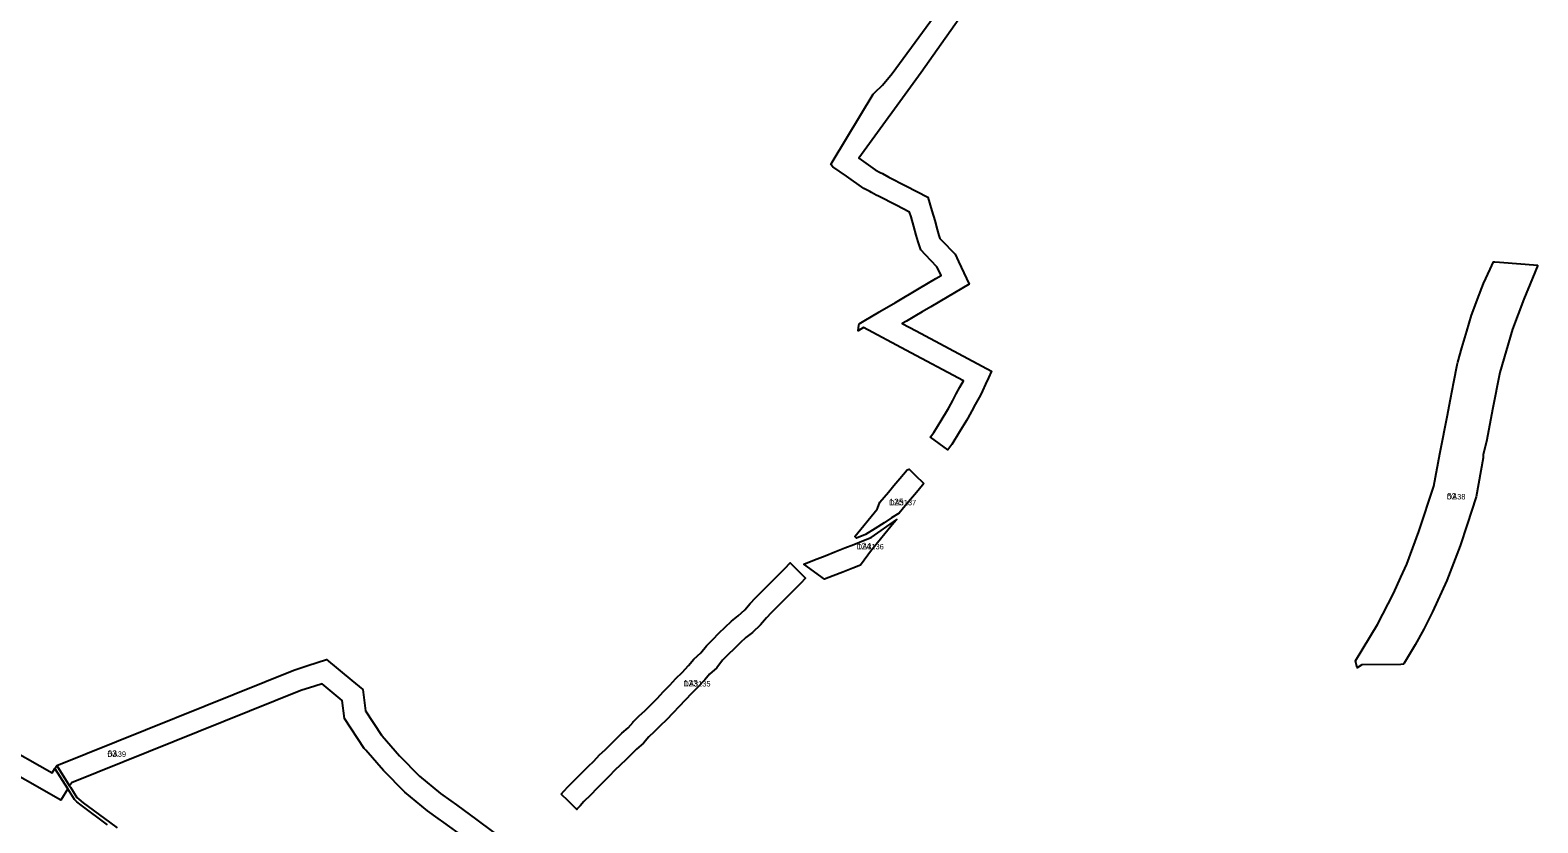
# Model space of a CAD drawing. Extents: x -537012 to -534603, y -1176562 to -1172739.
# Drawn here: x -535993 to -534603, y -1175871 to -1175140 of the extents above; entities that cross this region are included whole.
import ezdxf

# ---------------------------------------------------------------- set-up
doc = ezdxf.new("R2010")
doc.units = 0
for name, color, linetype in [('96120023', 7, 'Continuous'), ('96140023', 7, 'Continuous'), ('ID_VPO', 7, 'Continuous')]:
    doc.layers.add(name, color=color, linetype=linetype)

msp = doc.modelspace()

# ---------------------------------------------------------------- linework, layer by layer
at = {"layer": '96120023'}
msp.add_lwpolyline([(-535921.6, -1175873.09), (-535945.82, -1175855.15), (-535949.79, -1175851.94), (-535952.05, -1175849.98), (-535958.16, -1175840.1), (-535958.19, -1175840.06), (-535970.14, -1175821.39), (-535968.39, -1175818.56), (-535956.44, -1175837.23), (-535955.62, -1175838.5), (-535949.74, -1175848.02), (-535947.86, -1175849.64), (-535943.98, -1175852.77), (-535919.82, -1175870.67), (-535912.56, -1175875.93)], dxfattribs=at)
at = {"layer": '96140023'}
for points in [[(-535125.65, -1175114.54), (-535171.35, -1175179.43), (-535228.84, -1175258.49), (-535213.77, -1175269.12), (-535208.97, -1175271.6), (-535207.07, -1175272.72), (-535201.25, -1175275.98), (-535185.43, -1175284.03), (-535165.16, -1175294.32), (-535161.42, -1175307.02), (-535158.83, -1175315.85), (-535156.55, -1175324.14), (-535155.03, -1175329.66), (-535154.08, -1175332.44), (-535152.92, -1175333.64), (-535140.01, -1175347.02), (-535136.92, -1175353.62), (-535127.13, -1175374.47), (-535147.45, -1175386.52), (-535162.53, -1175395.44), (-535170.42, -1175400.1), (-535177.19, -1175404.11), (-535184.79, -1175408.61), (-535188.76, -1175410.94), (-535176.04, -1175417.7), (-535106.48, -1175454.72), (-535106.52, -1175454.81), (-535109.28, -1175460.96), (-535111.87, -1175466.75), (-535114.68, -1175473.01), (-535115.02, -1175473.77), (-535117.96, -1175479.18), (-535121.39, -1175485.47), (-535124.69, -1175491.52), (-535128.36, -1175498.25), (-535129.49, -1175500.32), (-535135.96, -1175510.86), (-535143.17, -1175522.62), (-535146.84, -1175527.49), (-535162.85, -1175515.62), (-535162.81, -1175515.45), (-535159.72, -1175511.35), (-535153.01, -1175500.4), (-535146.8, -1175490.29), (-535145.92, -1175488.67), (-535142.25, -1175481.94), (-535138.95, -1175475.89), (-535135.57, -1175469.7), (-535132.34, -1175463.62), (-535132.33, -1175463.62), (-535185.43, -1175435.36), (-535224.55, -1175414.58), (-535229.26, -1175417.53), (-535228.7, -1175412.38), (-535228.57, -1175411.16), (-535223.96, -1175408.45), (-535217.14, -1175404.43), (-535210.45, -1175400.5), (-535209.89, -1175400.17), (-535203.11, -1175396.18), (-535194.95, -1175391.38), (-535187.38, -1175386.9), (-535180.61, -1175382.89), (-535172.71, -1175378.22), (-535157.64, -1175369.31), (-535152.95, -1175366.53), (-535155.02, -1175362.12), (-535156.71, -1175358.52), (-535167.31, -1175347.53), (-535171.58, -1175343.11), (-535174.15, -1175335.54), (-535175.83, -1175329.46), (-535178.07, -1175321.32), (-535180.61, -1175312.66), (-535181.91, -1175308.25), (-535194.49, -1175301.86), (-535210.68, -1175293.62), (-535212.81, -1175292.54), (-535217.02, -1175290.07), (-535218.64, -1175289.12), (-535224.18, -1175286.25), (-535240.2, -1175274.95), (-535252.65, -1175266.55), (-535254.7, -1175264.4), (-535252.39, -1175260.55), (-535215.63, -1175199.34), (-535213.98, -1175197.78), (-535206.98, -1175191.18), (-535198.15, -1175180.48), (-535135.27, -1175094.64)], [(-535592.65, -1175884.69), (-535611.42, -1175871.09), (-535616.74, -1175867.23), (-535626.55, -1175860.34), (-535647.3, -1175843.08), (-535666.91, -1175823.04), (-535683.26, -1175804.38), (-535684.73, -1175802.68), (-535703.11, -1175775.1), (-535705.05, -1175758.49), (-535723.63, -1175743.14), (-535730.27, -1175745.43), (-535743.13, -1175749.36), (-535954.59, -1175834.56), (-535954.84, -1175834.66), (-535956.44, -1175837.23), (-535968.39, -1175818.56), (-535749.68, -1175730.47), (-535736.67, -1175726.21), (-535719.53, -1175720.59), (-535696.32, -1175739.98), (-535686.24, -1175748.4), (-535683.8, -1175768), (-535668.77, -1175790.56), (-535668.17, -1175791.26), (-535652.23, -1175809.44), (-535633.72, -1175828.36), (-535614.39, -1175844.44), (-535605.12, -1175850.96), (-535599.68, -1175854.9), (-535580.92, -1175868.49), (-535578.42, -1175870.31), (-535560.76, -1175883.69)], [(-536020.26, -1175798.17), (-535972.61, -1175825.36), (-535970.14, -1175821.39), (-535958.19, -1175840.06), (-535964.71, -1175850.59), (-536028.51, -1175814.18)]]:
    msp.add_lwpolyline(points, dxfattribs=at)
for points in [[(-534602.7, -1175357.11), (-534607.73, -1175369.2), (-534615.75, -1175388.41), (-534626.14, -1175416.23), (-534637.86, -1175456.11), (-534644.51, -1175490.19), (-534649.66, -1175518.02), (-534652.99, -1175531.91), (-534653.09, -1175534.8), (-534659.6, -1175570.59), (-534667.96, -1175596.16), (-534674.37, -1175615.81), (-534686.68, -1175647.91), (-534699.7, -1175676.93), (-534707.75, -1175692.79), (-534715.69, -1175707.17), (-534725.88, -1175724.1), (-534726.5, -1175725.15), (-534728.9, -1175725.2), (-534765, -1175725.6), (-534769.2, -1175728.4), (-534770.72, -1175721.95), (-534750.52, -1175688.37), (-534735.93, -1175659.99), (-534729.02, -1175644.76), (-534723.65, -1175632.94), (-534712.33, -1175602.64), (-534698.48, -1175560.95), (-534693.13, -1175530.98), (-534689.8, -1175514.09), (-534689.12, -1175510.64), (-534686.46, -1175497.02), (-534683.27, -1175480.7), (-534680.17, -1175464.82), (-534677.11, -1175449.15), (-534676.59, -1175446.48), (-534672.73, -1175433.39), (-534668.17, -1175417.92), (-534663.85, -1175403.25), (-534663.25, -1175401.65), (-534658.28, -1175388.31), (-534652.96, -1175374.04), (-534646.77, -1175360.91), (-534643.48, -1175353.92), (-534643.21, -1175353.95), (-534642.39, -1175354.01), (-534638.06, -1175354.31)], [(-535168.98, -1175558.56), (-535170.17, -1175559.99), (-535175.7, -1175566.61), (-535181.13, -1175573.11), (-535186.17, -1175579.15), (-535191.7, -1175585.77), (-535198.7, -1175590.23), (-535205.56, -1175594.61), (-535213.79, -1175599.86), (-535222.6, -1175605.49), (-535230.95, -1175608.71), (-535232.6, -1175607.35), (-535211.88, -1175582.03), (-535211.43, -1175581.48), (-535209.28, -1175575.61), (-535201.52, -1175566.33), (-535196.48, -1175560.29), (-535191.05, -1175553.79), (-535184.33, -1175545.74), (-535182.22, -1175545.09), (-535177.06, -1175550.34)], [(-535227.09, -1175633.62), (-535234.36, -1175636.5), (-535243.48, -1175640.11), (-535252.55, -1175643.71), (-535260.36, -1175646.8), (-535279.53, -1175632.88), (-535269.63, -1175628.96), (-535259.91, -1175625.11), (-535250.84, -1175621.52), (-535241.73, -1175617.91), (-535233.53, -1175614.66), (-535224.55, -1175611.11), (-535217.5, -1175608.32), (-535193.82, -1175591.54), (-535196.41, -1175594.7), (-535217.13, -1175620.02)], [(-535503.12, -1175844.96), (-535500.71, -1175842.26), (-535496.67, -1175837.74), (-535490.55, -1175831.73), (-535484.32, -1175825.2), (-535478.81, -1175819.87), (-535478.19, -1175819.27), (-535473.11, -1175814.36), (-535467.8, -1175808.78), (-535462.75, -1175803.92), (-535457.48, -1175798.84), (-535452.46, -1175793.8), (-535447.3, -1175788.74), (-535441.52, -1175783.7), (-535436.99, -1175778.38), (-535436.58, -1175777.9), (-535431.5, -1175773.03), (-535425.89, -1175767.64), (-535420.37, -1175762.32), (-535414.56, -1175756.25), (-535409.2, -1175750.56), (-535403.08, -1175744.29), (-535397.45, -1175738.23), (-535391.82, -1175732.67), (-535385.87, -1175726.27), (-535380.94, -1175720.41), (-535374.5, -1175714.58), (-535369.31, -1175708.05), (-535363.35, -1175702.16), (-535357.8, -1175696.49), (-535351.9, -1175691.02), (-535346.28, -1175685.46), (-535339.91, -1175680.56), (-535334, -1175674.87), (-535328.88, -1175668.99), (-535324.03, -1175663.79), (-535318.28, -1175657.99), (-535312.98, -1175652.65), (-535307.45, -1175647.28), (-535303.45, -1175643.39), (-535302.18, -1175642.08), (-535297.1, -1175636.81), (-535292.07, -1175631.59), (-535277.83, -1175645.64), (-535282.7, -1175650.69), (-535289.28, -1175657.51), (-535293.51, -1175661.62), (-535298.91, -1175666.87), (-535304.08, -1175672.07), (-535309.61, -1175677.65), (-535314.02, -1175682.38), (-535319.49, -1175688.67), (-535326.84, -1175695.74), (-535333.1, -1175700.55), (-535338.06, -1175705.47), (-535343.85, -1175710.83), (-535349.17, -1175716.27), (-535354.4, -1175721.43), (-535359.86, -1175728.31), (-535366.51, -1175734.33), (-535370.88, -1175739.52), (-535377.46, -1175746.6), (-535383.09, -1175752.16), (-535388.6, -1175758.08), (-535394.76, -1175764.4), (-535400.06, -1175770.02), (-535406.2, -1175776.44), (-535412.02, -1175782.05), (-535417.59, -1175787.4), (-535422.37, -1175792.05), (-535427.26, -1175797.8), (-535433.71, -1175803.43), (-535438.37, -1175808), (-535443.45, -1175813.1), (-535448.88, -1175818.32), (-535453.61, -1175822.89), (-535458.91, -1175828.45), (-535464.91, -1175834.25), (-535470.13, -1175839.3), (-535476.3, -1175845.77), (-535482.19, -1175851.55), (-535485.79, -1175855.58), (-535488.2, -1175858.28), (-535488.9, -1175859.05), (-535496.81, -1175851.22)]]:
    msp.add_lwpolyline(points, close=True, dxfattribs=at)

# ---------------------------------------------------------------- texts
for s, rotation, p in [('DA38', 0, (-534686.71, -1175573.14)), ('DA3137', 0, (-535200.79, -1175578.51)), ('DA3136', 360, (-535230.67, -1175619.17)), ('DA3135', 360, (-535390.47, -1175745.61)), ('DA39', 360, (-535921.69, -1175810.52))]:
    msp.add_text(s, height=5, rotation=rotation, dxfattribs=at).set_placement(p)
at = {"layer": 'ID_VPO'}
for s, rotation, p in [('62', 360, (-534686.71, -1175573.14)), ('125', 0, (-535200.79, -1175578.51)), ('124', 0, (-535230.67, -1175619.17)), ('123', 360, (-535390.47, -1175745.61)), ('63', 360, (-535921.69, -1175810.52))]:
    msp.add_text(s, height=6, rotation=rotation, dxfattribs=at).set_placement(p)

doc.saveas('drawing.dxf')
